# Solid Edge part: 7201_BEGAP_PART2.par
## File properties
Author: PARTuser1
Template: Normal.par
Last saved by: Francesco
Revision: 3
Application: Solid Edge
Material: Acciaio
Stile della faccia: Acciaio
Stile di riempimento: ANSI32(Acciaio)
Stile virtuale: Acciaio lavorato a macchina
Coef. of Thermal Exp: 0.0
Thermal Conductivity: 32.0
Specific Heat: 481.0
Modulus of Elasticity: 199947953000.0
Poisson's Ratio: 0.29
Yield Stress: 262000766.0
Ultimate Stress: 358527364.0
Elongation: 0.0
Tipo di contenuto documento: 0
Density: 7833,000 kg/m^3
Accuracy: 0,990
CADENASNORM: 7201 BEGAP_PART2
CADENAS_NB: 7201 BEGAP_PART2
CADENAS_NN: _PART2
CADENAS_NBSYN: 7201 BEGAP_PART2
CADENAS_LINA: 7201 BEGAP_PART2
CADENAS_Z: 10.000
CADENAS_Y0W2: 10.604
CADENAS_XIP: 0.000
CADENAS_XIN: 0.000
CADENAS_YIAC: 10.100
CADENAS_HIAC: 4.100
CADENAS_BEAC: 10.000
CADENAS_HI1: 2.250
CADENAS_R2I: 0.200
CADENAS_RWB: 3.000
CADENAS_XEP: 0.000
CADENAS_R2E: 0.100
CADENAS_Z0W2: 3.446
CADENAS_XEN: 0.000
CADENAS_RI: 3.000
CADENAS_X0WB: 5.000
CADENAS_RE: 3.000
CADENAS_C1E: 0.000
CADENAS_HE2: -16.000
CADENAS_HE1: 1.900
CADENAS_YEAC: 12.550
CADENAS_HEAC: 3.450
CADENAS_X0W2: 5.000
CADENAS_BOREDIAMETER: 12.000
CADENAS_BIAC: 10.000
CADENAS_BCH: 0.000
CADENAS_R1I: 0.600
CADENAS_PRODUCTID: 1210023201.000
CADENAS_BEARINGWIDTH: 10.000
CADENAS_R1E: 0.300
CADENAS_Y0WE: 11.150
CADENAS_Y0WB: 11.150
CADENAS_X0IP: 5.000
CADENAS_Y0IAC: 11.150
CADENAS_comment: design:acbb1; version:5000.3; lang:it; selectedUnitParts:000000; action:download; skf2d3daction.jsp version:2008-03-06; getRequestURI:/skf/skf3dnew/skf2d3daction.jsp
CADENAS_KT: DUMMY
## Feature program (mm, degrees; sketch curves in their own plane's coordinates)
sketch for "unnamed RevolvedProtrusion 1" plane through (0, 0, 0) normal (0, 0, 1) x-axis (1, 0, 0)
  line (0, 15.7) -> (0, 12.85)
  line (0, 12.85) -> (0.3, 12.55)
  line (0.3, 12.55) -> (2.3467, 12.55)
  arc centre (5, 11.15) radius 3 from (2.3467, 12.55) to (5.5454, 14.1) cw
  line (5.5454, 14.1) -> (9.9, 14.1)
  arc centre (9.9, 14.2) radius 0.1 from (9.9, 14.1) to (10, 14.2) ccw
  line (10, 14.2) -> (10, 15.7)
  arc centre (9.7, 15.7) radius 0.3 from (10, 15.7) to (9.7, 16) ccw
  line (9.7, 16) -> (0.3, 16)
  arc centre (0.3, 15.7) radius 0.3 from (0.3, 16) to (0, 15.7) ccw
revolve "unnamed RevolvedProtrusion 1" add finite 360 deg about sketch line (10, 0) -> (0, 0)
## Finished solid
Body 1: solid body, 10 faces, 10 edges, 0 vertices.
  Faces by surface: torus 4, cylinder 3, plane 2, cone 1
  Edges by curve: circle 10
Bounding box of the edges (mm; curved faces can reach further): 10.000 x 32.000 x 32.000, from (0, -16, -16) to (10, 16, 16).
Cylindrical faces by radius (mm): R12.55 x1, R14.1 x1, R16 x1
Conical faces (half-angle, radius in mm at the cone's reference point): 45 deg R12.85 x1
Toroidal faces (ring radius, tube radius in mm): R11.15 r3 x1, R14.2 r0.1 x1, R15.7 r0.3 x2
Planar faces by outward normal: +x 1, -x 1
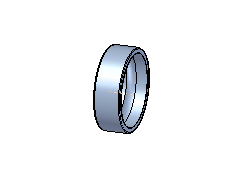
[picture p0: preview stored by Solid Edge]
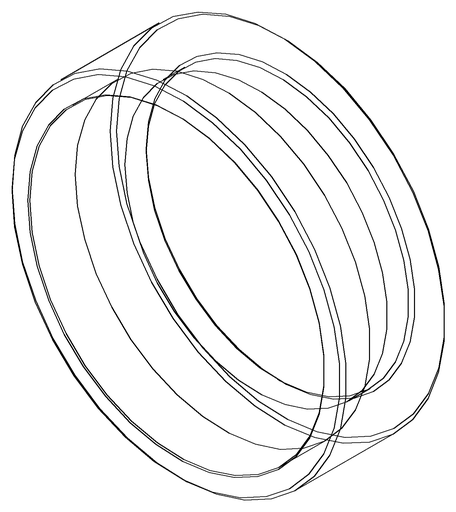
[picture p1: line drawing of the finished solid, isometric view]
